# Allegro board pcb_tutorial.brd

Outline 100 x 50 mm; copper layers: TOP, POWERPLANE_1, BOTTOM. Coordinates in mm from the lower left corner of the outline.
Outline path: rectangle 0,0 100,50

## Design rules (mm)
constraint set DEFAULT: min track width 0.127
net group DPD: nets D+ D-

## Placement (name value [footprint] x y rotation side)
C1  10uF  [0402-CAP]  12 36 270 top
C2  100uF  [1210]  7 30 0 top
C3  10uF  [0402-CAP]  35 19 180 top
C4  0.1uF  [0402-CAP]  5 20 0 top
C5  0.1uF  [0402-CAP]  5 17 0 top
C6  0.1uF  [0402-CAP]  10 41 90 top
C7  0.1uF  [0402-CAP]  33 27 90 top
C8  0.1uF  [0402-CAP]  7 41 90 top
C9  10uF  [0402-CAP]  11 26 180 top
IC1  PIC32MX440F512H  [SQFP-S-10X10-64]  21 25 90 top
JP1  -  [XTEND-DIGI-MODEM]  69 25 0 top
JP2  PIC 32 PROG  [1X06_LOCK]  16 11 0 top
MAIN_PWR  LED  [LED_LNJ]  24 4 90 top
NOREF  -  [unnamed]  96 4 0 top
NOREF#2  -  [unnamed]  96 46 0 top
NOREF#3  -  [unnamed]  4 46 0 top
NOREF#4  -  [unnamed]  4 4 0 top
NOREF#5  -  [#2]  0 50 0 top
NOREF#6  -  [#2]  -24 -101 0 top
NOREF#7  -  [#2]  0 0 90 top
R1  150  [0402-RES]  20 4 90 top
R2  56k  [0402-RES]  35 22 180 top
U1  LT1965EMS8E-1P5  [MSOP_8_ADI]  6 36 0 top
X1  USB-B  [USB-MICROB]  20 46 180 top
Y1  8MHz  [CRYSTAL-SMD]  22 36 270 top

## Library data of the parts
C1-C9 = CAP NP
IC1 = PIC32MX440F512H
JP1 = XTEND-DIGI-MODEM
JP2 = M06_LOCK
MAIN_PWR = LED
R1 R2 = RESISTOR
U1 = LT1965EMS8E-1P5_1
X1 = USB-MICROB
Y1 = CRYSTAL

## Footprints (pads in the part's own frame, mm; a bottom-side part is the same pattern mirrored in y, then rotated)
1X06_LOCK
  round 1.88 hole 1.016: 1(0,0) 2(2.54,-0.254) 3(5.08,0) 4(7.62,-0.254) 5(10.16,0) 6(12.7,-0.254)
0402-CAP
  rect 0.7x0.9 smd: 1(-0.65,0) 2(0.65,0)
0402-RES
  rect 0.7x0.9 smd: 1(-0.65,0) 2(0.65,0)
1210
  rect 1.2x2 smd: 1(-1.6,0) 2(1.6,0)
CRYSTAL-SMD
  rect 1.1x1.9 smd: 1(-1.15,1.85) 2(-1.15,-1.85) 3(1.15,-1.85) 4(1.15,1.85)
LED_LNJ
  rect 0.445x0.95 smd: 1(-0.652,0) 2(0.652,0)
MSOP_8_ADI
  rect 1.31x0.431 smd: 1(-2.235,0.975) 2(-2.235,0.325) 3(-2.235,-0.325) 4(-2.235,-0.975) 5(2.235,-0.975) 6(2.235,-0.325) 7(2.235,0.325) 8(2.235,0.975)
SQFP-S-10X10-64
  rect 1.6x0.295 smd: 1(-5.6,3.75) 2(-5.6,3.25) 3(-5.6,2.75) 4(-5.6,2.25) 5(-5.6,1.75) 6(-5.6,1.25) 7(-5.6,0.75) 8(-5.6,0.25) 9(-5.6,-0.25) 10(-5.6,-0.75) 11(-5.6,-1.25) 12(-5.6,-1.75) 13(-5.6,-2.25) 14(-5.6,-2.75) 15(-5.6,-3.25) 16(-5.6,-3.75) 33(5.6,-3.75) 34(5.6,-3.25) 35(5.6,-2.75) 36(5.6,-2.25) 37(5.6,-1.75) 38(5.6,-1.25) 39(5.6,-0.75) 40(5.6,-0.25) 41(5.6,0.25) 42(5.6,0.75) 43(5.6,1.25) 44(5.6,1.75) 45(5.6,2.25) 46(5.6,2.75) 47(5.6,3.25) 48(5.6,3.75)
  rect 0.295x1.6 smd: 17(-3.75,-5.6) 18(-3.25,-5.6) 19(-2.75,-5.6) 20(-2.25,-5.6) 21(-1.75,-5.6) 22(-1.25,-5.6) 23(-0.75,-5.6) 24(-0.25,-5.6) 25(0.25,-5.6) 26(0.75,-5.6) 27(1.25,-5.6) 28(1.75,-5.6) 29(2.25,-5.6) 30(2.75,-5.6) 31(3.25,-5.6) 32(3.75,-5.6) 49(3.75,5.6) 50(3.25,5.6) 51(2.75,5.6) 52(2.25,5.6) 53(1.75,5.6) 54(1.25,5.6) 55(0.75,5.6) 56(0.25,5.6) 57(-0.25,5.6) 58(-0.75,5.6) 59(-1.25,5.6) 60(-1.75,5.6) 61(-2.25,5.6) 62(-2.75,5.6) 63(-3.25,5.6) 64(-3.75,5.6)
unnamed
  round 4.064 hole 3.81: (0,0)
USB-MICROB
  rect 0.35x1.4 smd: D+(0,2.65) D-(-0.65,2.65) GND(1.3,2.65) ID(0.65,2.65) VBUS(-1.3,2.65)
  rect 1.8x1.9 smd: MT1(-3.8,0) MT2(3.8,0)
  rect 2.1x1.6 smd: MT3(-3.1,2.55) MT4(3.1,2.55)
  rect 1.9x1.9 smd: P_1(-1.2,0) P_2(1.2,0)
XTEND-DIGI-MODEM
  round 0 hole 3.3 unplated: (-26.5,14.5) (-26.5,-14.5) (26.5,14.5) (26.5,-14.5)
  round 1.422 hole 0.7: 1(-27.5,9) 2(-25.5,9) 3(-27.5,7) 4(-25.5,7) 5(-27.5,5) 6(-25.5,5) 7(-27.5,3) 8(-25.5,3) 9(-27.5,1) 10(-25.5,1) 11(-27.5,-1) 12(-25.5,-1) 13(-27.5,-3) 14(-25.5,-3) 15(-27.5,-5) 16(-25.5,-5) 17(-27.5,-7) 18(-25.5,-7) 19(-27.5,-9) 20(-25.5,-9)

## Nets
3.3V: C2.1 C4.1 C5.1 C6.1 C7.1 C8.1 IC1.10 IC1.19 IC1.26 IC1.35 IC1.38 JP2.2 R1.1 R2.2 U1.1 U1.2 U1.3(\SENSE/ADJ*\)
GND: C1.2 C2.2 C3.2 C4.2 C5.2 C6.2 C7.2 C8.2 C9.2 IC1.9 IC1.20 IC1.25 IC1.41 JP1.1 JP2.3 MAIN_PWR.1(\CATHODE\) U1.4 U1.5 X1.GND Y1.2 Y1.4(\GND_4\)
VBUS: C1.1 IC1.34 JP1.2(\VCC\) U1.6 U1.7 U1.8 X1.VBUS(\VBUS\)
CTS: IC1.21 JP1.9
D+: IC1.37 X1.D+
D-: IC1.36 X1.D-
PROG0: IC1.17 JP2.5
PROG1: IC1.18 JP2.4
RESET: IC1.7(\_MCLR\) JP2.1
RTS: IC1.29 JP1.10
SHDN: IC1.59 JP1.7
URX: IC1.31 JP1.6
UTX: IC1.32 JP1.5
N01899: MAIN_PWR.2 R1.2
N02098: IC1.39 Y1.1
N02102: IC1.40 Y1.3
N02114: C9.1 IC1.56
N02189: C3.1 JP1.11 R2.1

Pads without a net: IC1 1 2 3 4 5 6 8 11 12 13 14 15 16 22 23 24 27 28 30 33 42 43 44 45 46 47 48 49 50 51 52 53 54 55 57 58 60 61 62 63 64; JP1 3 4 8 12 13 14 15 16 17 18 19 20; JP2 6; X1 ID MT1 MT2 MT3 MT4 P_1 P_2

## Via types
v1: diameter 0.61, hole 0.33, TOP to BOTTOM, 31 vias

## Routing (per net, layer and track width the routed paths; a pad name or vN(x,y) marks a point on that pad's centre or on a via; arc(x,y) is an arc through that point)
3.3V: length 20.6
  TOP w0.28: IC1.26 v1(27.83,25.75) ; IC1.10 v1(21.75,17.63) ; IC1.19 v1(28.37,22.25)
  TOP w0.381: R2.2 v1(33.57,22) ; C4.1 v1(3.57,20) ; v1(2.68,36.98) U1.1 U1.2 U1.3 ; C8.1 v1(7,39.57) ; IC1.35 v1(23.75,31.83) ; C2.1 v1(4.37,30) ; R1.1 v1(20,2.57) ; C5.1 v1(3.57,17) ; IC1.38 v1(22.25,31.83) ; C6.1 v1(10,39.57) ; C7.1 v1(33,25.57)
  POWERPLANE_1 w0.381: 18.54,9.63 JP2.2 ; JP2.2 18.54,11.86 ; JP2.2 17.42,10.75 ; JP2.2 19.66,10.75
GND: length 43.3
  TOP w0.28: v1(20.8,20.91) 21.25,20.45 IC1.9 ; IC1.25 v1(24.61,25.25) ; IC1.20 25.29,22.75 25.23,22.81 v1(24.61,22.81)
  TOP w0.381: MAIN_PWR.1 v1(24,2.69) ; X1.GND v1(18.7,42.22) ; C4.2 v1(6.43,20) ; C7.2 v1(33,28.43) ; U1.4 v1(2.68,35.02) ; C9.2 v1(9.57,26) ; U1.5 v1(9.32,35.02) ; IC1.41 v1(20.75,31.83) 18.88,33.7 18.88,36.28 19.75,37.15 Y1.2 20.55,37.15 21.32,37.92 21.32,38.32 21.73,38.73 24.21,38.73 25.4,37.55 25.4,36 24.25,34.85 Y1.4 ; C2.2 v1(9.63,30) ; C5.2 v1(6.43,17) ; C6.2 v1(10,42.43) ; C3.2 v1(33.57,19) ; C1.2 v1(12,34.57) ; C8.2 v1(7,42.43)
  BOTTOM w0.381: 19.96,11 JP2.3 ; JP2.3 22.2,11 ; JP2.3 21.08,9.88 ; JP2.3 21.08,12.12 ; JP1.1 41.5,34.89 ; JP1.1 40.61,34 ; JP1.1 42.39,34 ; JP1.1 41.5,33.11
VBUS: length 58.8
  TOP w0.127: JP1.2 42.6,34.9 41.13,34.9 41.1,34.88 28.41,34.88 ; 23.8,29.16 24.25,29.61 IC1.34 ; 23.8,29.16 24.53,29.16 28.41,33.05 28.41,34.88 ; 23.8,29.16 17.47,29.16 14.45,32.19 14.45,34.88 12.67,36.65 C1.1 11.36,36.65 11.03,36.33 U1.7 ; U1.7 U1.8 ; U1.7 U1.6 ; 28.41,34.88 28.41,36.71 24.49,40.64 23.48,40.64 21.3,42.83 X1.VBUS
CTS: length 16
  TOP w0.127: JP1.9 39.86,26 37.11,23.25 IC1.21
D+: length 18.7
  TOP w0.127: X1.D+ 20,41.87 22.12,39.75 24.66,39.75 26.42,37.99 26.42,35.03 25.29,33.91 24.77,33.91 22.75,31.89 IC1.37
D-: length 18.5
  TOP w0.127: IC1.36 23.25,32.03 24.87,33.66 25.4,33.66 25.47,33.73 25.5,33.73 26.67,34.9 26.67,38.1 24.77,40.01 22.23,40.01 20.65,41.58 X1.D-
PROG0: length 10.4
  TOP w0.127: IC1.17 26.6,20.91 26.16,20.47 JP2.5
PROG1: length 12.8
  TOP w0.127: IC1.18 25.61,21.75 25.24,21.38 25.24,12.37 JP2.4
RESET: length 10.2
  TOP w0.127: JP2.1 16,14.16 20.25,18.41 IC1.7
RTS: length 17.4
  TOP w0.127: JP1.10 42.6,26.9 30.04,26.9 29.69,27.25 IC1.29
SHDN: length 36.5
  TOP w0.127: IC1.59 19.83,23.75 26.98,30.9 43.87,30.9 44.4,30.37 44.4,29.63 43.87,29.1 42.6,29.1 JP1.7
URX: length 17.6
  TOP w0.127: JP1.6 43.14,30 42.24,29.1 31.53,29.1 30.68,28.25 IC1.31
UTX: length 15.4
  TOP w0.127: IC1.32 30.55,28.75 31.8,30 JP1.5
N01899: length 4
  TOP w0.127: MAIN_PWR.2 20.64,4.65 20.64,4.65 R1.2
N02098: length 7.8
  TOP w0.127: IC1.39 21.75,34.52 22.82,35.59 23.42,35.59 23.85,36.02 Y1.1
N02102: length 7.4
  TOP w0.127: Y1.3 20.15,34.11 20.28,33.98 21.37,33.98 21.5,33.86 21.5,33.6 21.37,33.47 20.28,33.47 20.15,33.35 20.15,33.15 20.28,33.02 20.75,33.02 21.25,32.52 IC1.40
N02114: length 4.1
  TOP w0.127: C9.1 13.66,26 14.41,25.25 IC1.56
N02189: length 9.7
  TOP w0.127: C3.1 R2.1 39.5,22 JP1.11

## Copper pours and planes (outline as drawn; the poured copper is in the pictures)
3.3V on POWERPLANE_1: 0.3,49.7 99.7,49.7 99.7,0.3 0.3,0.3
GND on BOTTOM: 0.3,49.7 99.7,49.7 99.7,0.3 0.3,0.3

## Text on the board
User.Comments: A | EMA Design Automation | 225 Tech Park Drive | Rochester, NY, 14623 | EMA-123 | 1 of 1
XSECTION_CHART: *  SURFACE | L1 TOP CONDUCTOR | *  DIELECTRIC | L2 POWERPLANE_1 PLANE | L3 BOTTOM CONDUCTOR | DESIGN CROSS SECTION CHART | ___________________________ | TOTAL THICKNESS 0.49784 MM | 1-3
DIMENSION: FIGURE | FINISHED_SIZE | 0.3302 | 0.7 | 1.016 | 3.81 | 3.3 | DRILL CHART: TOP to BOTTOM | ALL UNITS ARE IN MILLIMETERS | PLATED | NON-PLATED | QTY | 31 | 20 | 6 | 4
